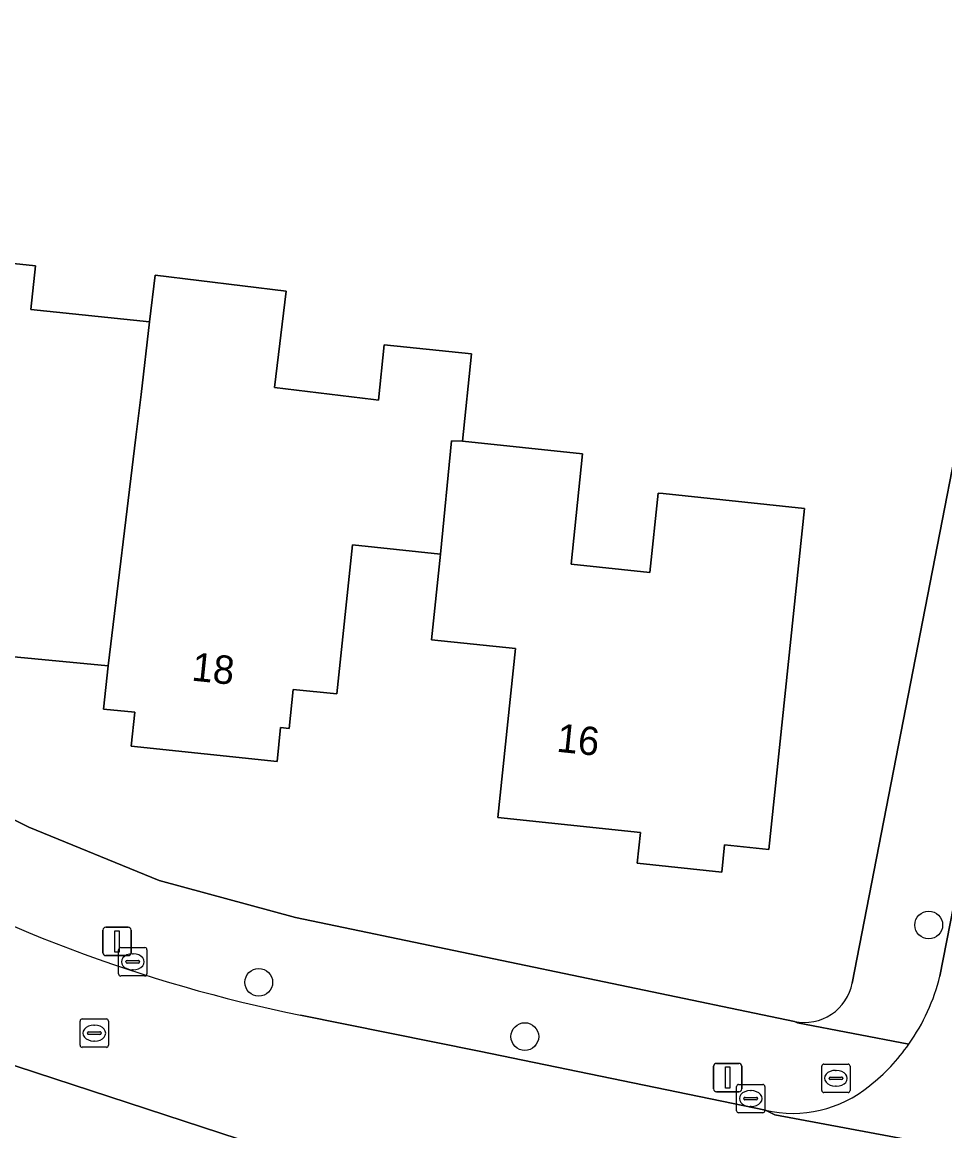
# Model space of a CAD drawing. Extents: x 162396 to 163643, y 386452 to 387406.
# Drawn here: x 162942.76 to 162975.29, y 386904.9 to 386943.96 of the extents above; entities that cross this region are included whole.
import ezdxf

# ---------------------------------------------------------------- set-up
doc = ezdxf.new("R2010")
doc.units = 0
for name, color, linetype in [('IMGEO_Boom', 7, 'Continuous'), ('IMGEO_Brandkraan', 7, 'Continuous'), ('IMGEO_Erf', 7, 'Continuous'), ('IMGEO_Kolk', 7, 'Continuous'), ('IMGEO_Lichtmast', 7, 'Continuous'), ('IMGEO_Pand', 7, 'Continuous'), ('IMGEO_Pand_nummerreeks', 7, 'Continuous'), ('IMGEO_Rijbaan_lokaal_open', 7, 'Continuous'), ('IMGEO_Rioolput', 7, 'Continuous'), ('IMGEO_Voetpad_open', 7, 'Continuous')]:
    doc.layers.add(name, color=color, linetype=linetype)

msp = doc.modelspace()

# ---------------------------------------------------------------- linework, layer by layer
at = {"layer": 'IMGEO_Boom'}
for centre in [(162974.721, 386912.151), (162951.105, 386910.133), (162960.482, 386908.221)]:
    msp.add_circle(centre, 0.489, dxfattribs=at)
at = {"layer": 'IMGEO_Brandkraan'}
for p, q in [((162970.948, 386906.324), (162970.948, 386907.176)), ((162971.023, 386907.25), (162971.875, 386907.25)), ((162971.436, 386907.03), (162971.461, 386907.03)), ((162971.949, 386907.176), (162971.949, 386906.324)), ((162971.207, 386906.744), (162971.207, 386906.756)), ((162971.645, 386906.707), (162971.247, 386906.707)), ((162971.25, 386906.793), (162971.648, 386906.793)), ((162971.691, 386906.756), (162971.691, 386906.744)), ((162971.875, 386906.25), (162971.023, 386906.25)), ((162971.459, 386906.47), (162971.434, 386906.47))]:
    msp.add_line(p, q, dxfattribs=at)
for points in [[(162970.948, 386906.324), (162970.948, 386907.176)], [(162971.023, 386907.25), (162971.875, 386907.25)], [(162971.949, 386907.176), (162971.949, 386906.324)], [(162971.875, 386906.25), (162971.023, 386906.25)]]:
    msp.add_lwpolyline(points, dxfattribs=at)
for centre, radius, start, end in [((162971.025, 386907.174), 0.0765, 91.552, 178.448), ((162971.025, 386907.174), 0.0765, 91.552, 178.448), ((162971.873, 386907.174), 0.0765, 1.552, 88.448), ((162971.873, 386907.174), 0.0765, 1.552, 88.448), ((162971.247, 386906.753), 0.0403, 85.8775, 175.7526), ((162971.244, 386906.743), 0.0366, 178.938, 274.7102), ((162971.648, 386906.75), 0.043, 264.8664, 352.4533), ((162971.652, 386906.755), 0.0386, 1.7309, 96.639), ((162971.025, 386906.326), 0.0765, 181.552, 268.448), ((162971.025, 386906.326), 0.0765, 181.552, 268.448), ((162971.873, 386906.326), 0.0765, 271.552, 358.448), ((162971.873, 386906.326), 0.0765, 271.552, 358.448)]:
    msp.add_arc(centre, radius, start, end, dxfattribs=at)
for centre, major_axis, ratio, start_param, end_param in [((162971.435, 386906.75), (-0.387, 0.002), 0.722429, 4.712389, 7.853982), ((162971.46, 386906.75), (-0.39, 0.002), 0.717154, 1.570796, 4.712389)]:
    msp.add_ellipse(centre, major_axis=major_axis, ratio=ratio, start_param=start_param, end_param=end_param, dxfattribs=at)
at = {"layer": 'IMGEO_Erf'}
for points in [[(162972.023, 386910.108), (162989.528, 387000)], [(162938.889, 386935.832), (162943.233, 386935.379), (162943.073, 386933.841), (162947.256, 386933.404), (162947.456, 386935.045), (162952.066, 386934.484), (162951.653, 386931.092), (162955.145, 386930.667), (162955.326, 386930.645), (162955.529, 386932.589), (162958.603, 386932.269), (162958.283, 386929.195), (162962.519, 386928.753), (162962.113, 386924.861), (162964.894, 386924.571), (162965.185, 386927.367), (162965.363, 386927.348), (162970.336, 386926.83), (162969.083, 386914.816), (162967.524, 386914.979), (162967.423, 386914.016), (162964.444, 386914.327), (162964.558, 386915.416), (162959.532, 386915.94), (162960.153, 386921.893), (162957.193, 386922.202), (162957.508, 386925.217), (162954.404, 386925.541), (162953.856, 386920.291), (162952.313, 386920.452), (162952.17, 386919.077), (162951.872, 386919.108), (162951.748, 386917.916), (162946.608, 386918.451), (162946.732, 386919.644), (162945.637, 386919.758), (162945.795, 386921.277), (162937.784, 386922.045)], [(162905.757, 386934.385), (162943, 386915.598), (162947.592, 386913.72), (162952.4, 386912.414), (162969.989, 386908.754)]]:
    msp.add_lwpolyline(points, dxfattribs=at)
msp.add_arc((162970.34, 386910.431), 1.714, 258.1769, 349.1251, dxfattribs=at)
at = {"layer": 'IMGEO_Kolk'}
for p, q in [((162946.238, 386911.355), (162947.09, 386911.355)), ((162946.163, 386910.429), (162946.163, 386911.281)), ((162946.651, 386911.135), (162946.676, 386911.135)), ((162947.164, 386911.281), (162947.164, 386910.429)), ((162946.422, 386910.849), (162946.422, 386910.861)), ((162946.86, 386910.812), (162946.462, 386910.812)), ((162946.465, 386910.898), (162946.863, 386910.898)), ((162946.674, 386910.575), (162946.649, 386910.575)), ((162946.906, 386910.861), (162946.906, 386910.849)), ((162947.09, 386910.355), (162946.238, 386910.355)), ((162967.944, 386905.61), (162967.944, 386906.462)), ((162968.019, 386906.536), (162968.871, 386906.536)), ((162968.432, 386906.316), (162968.457, 386906.316)), ((162968.945, 386906.462), (162968.945, 386905.61)), ((162968.203, 386906.03), (162968.203, 386906.042)), ((162968.641, 386905.993), (162968.243, 386905.993)), ((162968.246, 386906.079), (162968.644, 386906.079)), ((162968.687, 386906.042), (162968.687, 386906.03)), ((162968.871, 386905.536), (162968.019, 386905.536)), ((162968.455, 386905.756), (162968.43, 386905.756))]:
    msp.add_line(p, q, dxfattribs=at)
for points in [[(162946.238, 386911.355), (162947.09, 386911.355)], [(162946.163, 386910.429), (162946.163, 386911.281)], [(162947.164, 386911.281), (162947.164, 386910.429)], [(162947.09, 386910.355), (162946.238, 386910.355)], [(162967.944, 386905.61), (162967.944, 386906.462)], [(162968.019, 386906.536), (162968.871, 386906.536)], [(162968.945, 386906.462), (162968.945, 386905.61)], [(162968.871, 386905.536), (162968.019, 386905.536)]]:
    msp.add_lwpolyline(points, dxfattribs=at)
for centre, radius, start, end in [((162946.24, 386911.279), 0.0765, 91.552, 178.448), ((162946.24, 386911.279), 0.0765, 91.552, 178.448), ((162947.088, 386911.279), 0.0765, 1.552, 88.448), ((162947.088, 386911.279), 0.0765, 1.552, 88.448), ((162946.462, 386910.858), 0.0403, 85.8775, 175.7526), ((162946.459, 386910.848), 0.0366, 178.938, 274.7102), ((162946.863, 386910.855), 0.043, 264.8664, 352.4533), ((162946.867, 386910.86), 0.0386, 1.7309, 96.639), ((162946.24, 386910.431), 0.0765, 181.552, 268.448), ((162946.24, 386910.431), 0.0765, 181.552, 268.448), ((162947.088, 386910.431), 0.0765, 271.552, 358.448), ((162947.088, 386910.431), 0.0765, 271.552, 358.448), ((162968.021, 386906.46), 0.0765, 91.552, 178.448), ((162968.021, 386906.46), 0.0765, 91.552, 178.448), ((162968.869, 386906.46), 0.0765, 1.552, 88.448), ((162968.869, 386906.46), 0.0765, 1.552, 88.448), ((162968.243, 386906.039), 0.0403, 85.8775, 175.7526), ((162968.24, 386906.029), 0.0366, 178.938, 274.7102), ((162968.644, 386906.036), 0.043, 264.8664, 352.4533), ((162968.648, 386906.041), 0.0386, 1.7309, 96.639), ((162968.021, 386905.612), 0.0765, 181.552, 268.448), ((162968.021, 386905.612), 0.0765, 181.552, 268.448), ((162968.869, 386905.612), 0.0765, 271.552, 358.448), ((162968.869, 386905.612), 0.0765, 271.552, 358.448)]:
    msp.add_arc(centre, radius, start, end, dxfattribs=at)
for centre, major_axis, ratio, start_param, end_param in [((162946.65, 386910.855), (-0.387, 0.002), 0.722429, 4.712389, 7.853982), ((162946.675, 386910.855), (-0.39, 0.002), 0.717154, 1.570796, 4.712389), ((162968.431, 386906.036), (-0.387, 0.002), 0.722429, 4.712389, 7.853982), ((162968.456, 386906.036), (-0.39, 0.002), 0.717154, 1.570796, 4.712389)]:
    msp.add_ellipse(centre, major_axis=major_axis, ratio=ratio, start_param=start_param, end_param=end_param, dxfattribs=at)
at = {"layer": 'IMGEO_Lichtmast'}
for p, q in [((162945.611, 386911.172), (162945.611, 386911.972)), ((162945.611, 386911.972), (162945.611, 386911.172)), ((162945.711, 386912.072), (162946.501, 386912.072)), ((162946.501, 386912.072), (162945.711, 386912.072)), ((162946.601, 386911.972), (162946.601, 386911.172)), ((162946.601, 386911.172), (162946.601, 386911.972)), ((162946.501, 386911.072), (162945.711, 386911.072)), ((162945.711, 386911.072), (162946.501, 386911.072)), ((162967.138, 386906.376), (162967.138, 386907.176)), ((162967.138, 386907.176), (162967.138, 386906.376)), ((162967.238, 386907.276), (162968.028, 386907.276)), ((162968.028, 386907.276), (162967.238, 386907.276)), ((162968.128, 386907.176), (162968.128, 386906.376)), ((162968.128, 386906.376), (162968.128, 386907.176)), ((162968.028, 386906.276), (162967.238, 386906.276)), ((162967.238, 386906.276), (162968.028, 386906.276))]:
    msp.add_line(p, q, dxfattribs=at)
for points in [[(162946.031, 386911.947), (162946.181, 386911.947), (162946.181, 386911.197), (162946.031, 386911.197), (162946.031, 386911.947)], [(162967.558, 386907.151), (162967.708, 386907.151), (162967.708, 386906.401), (162967.558, 386906.401), (162967.558, 386907.151)]]:
    msp.add_lwpolyline(points, dxfattribs=at)
for centre, start, end in [((162945.711, 386911.972), 90, 180), ((162945.711, 386911.972), 90, 180), ((162946.501, 386911.972), 0, 90), ((162946.501, 386911.972), 360, 90), ((162945.711, 386911.172), 180, 270), ((162945.711, 386911.172), 180, 270), ((162946.501, 386911.172), 270, 0), ((162946.501, 386911.172), 270, 0), ((162967.238, 386907.176), 90, 180), ((162967.238, 386907.176), 90, 180), ((162968.028, 386907.176), 0, 90), ((162968.028, 386907.176), 360, 90), ((162967.238, 386906.376), 180, 270), ((162967.238, 386906.376), 180, 270), ((162968.028, 386906.376), 270, 0), ((162968.028, 386906.376), 270, 0)]:
    msp.add_arc(centre, 0.1, start, end, dxfattribs=at)
at = {"layer": 'IMGEO_Pand'}
for points in [[(162947.256, 386933.404), (162943.073, 386933.841), (162943.233, 386935.379), (162938.889, 386935.832), (162938.919, 386936.121), (162935.975, 386936.428), (162935.219, 386929.208), (162938.496, 386928.866), (162937.914, 386923.288), (162937.784, 386922.045), (162945.795, 386921.277), (162946.776, 386929.332), (162946.954, 386930.845)], [(162954.404, 386925.541), (162957.508, 386925.217), (162957.898, 386929.209), (162958.283, 386929.195), (162958.603, 386932.269), (162955.529, 386932.589), (162955.326, 386930.645), (162955.145, 386930.667), (162951.653, 386931.092), (162952.066, 386934.484), (162947.456, 386935.045), (162947.256, 386933.404), (162946.954, 386930.845), (162946.776, 386929.332), (162945.795, 386921.277), (162945.637, 386919.758), (162946.732, 386919.644), (162946.608, 386918.451), (162951.748, 386917.916), (162951.872, 386919.108), (162952.17, 386919.077), (162952.313, 386920.452), (162953.856, 386920.291)], [(162957.898, 386929.209), (162957.508, 386925.217), (162957.193, 386922.202), (162960.153, 386921.893), (162959.532, 386915.94), (162964.558, 386915.416), (162964.444, 386914.327), (162967.423, 386914.016), (162967.524, 386914.979), (162969.083, 386914.816), (162970.336, 386926.83), (162965.363, 386927.348), (162965.185, 386927.367), (162964.894, 386924.571), (162962.113, 386924.861), (162962.519, 386928.753), (162958.283, 386929.195)]]:
    msp.add_lwpolyline(points, close=True, dxfattribs=at)
at = {"layer": 'IMGEO_Rijbaan_lokaal_open'}
for points in [[(162993.351, 387003.708), (162992.593, 387000), (162990.936, 386991.471), (162990.218, 386987.772), (162987.431, 386973.419), (162985.908, 386965.577), (162983.057, 386950.899), (162982.357, 386947.293), (162975.116, 386910.354)], [(162901.826, 386926.95), (162904.027, 386925.887), (162937.007, 386909.322), (162938.667, 386908.445), (162951.708, 386904.178), (162954.151, 386903.61), (163000, 386894.601), (163000.585, 386894.482)], [(163015.114, 386895.272), (163013.969, 386895.696), (163009.769, 386897.129), (163003.361, 386898.96), (163000, 386899.64), (162985.263, 386902.621), (162985.093, 386902.521), (162969.299, 386905.46), (162968.963, 386905.626), (162958.875, 386907.712), (162952.574, 386908.978)], [(162951.708, 386904.178), (162938.667, 386908.445)], [(162968.963, 386905.626), (162969.299, 386905.46), (162985.093, 386902.521), (162985.263, 386902.621)]]:
    msp.add_lwpolyline(points, dxfattribs=at)
for centre, radius, start, end in [((162962.901, 386960.241), 52.293, 240.0812, 258.6099), ((162968.219, 386912.053), 7.103, 324.7686, 346.1636), ((162968.216, 386912.041), 7.099, 308.466, 324.8575), ((162969.93, 386909.768), 4.253, 256.8567, 309.438)]:
    msp.add_arc(centre, radius, start, end, dxfattribs=at)
at = {"layer": 'IMGEO_Rioolput'}
for p, q in [((162944.806, 386907.916), (162944.806, 386908.768)), ((162944.881, 386908.842), (162945.733, 386908.842)), ((162945.294, 386908.622), (162945.319, 386908.622)), ((162945.807, 386908.768), (162945.807, 386907.916)), ((162945.065, 386908.336), (162945.065, 386908.348)), ((162945.503, 386908.299), (162945.105, 386908.299)), ((162945.108, 386908.385), (162945.506, 386908.385)), ((162945.549, 386908.348), (162945.549, 386908.336)), ((162945.733, 386907.842), (162944.881, 386907.842)), ((162945.317, 386908.062), (162945.292, 386908.062))]:
    msp.add_line(p, q, dxfattribs=at)
for points in [[(162944.806, 386907.916), (162944.806, 386908.768)], [(162944.881, 386908.842), (162945.733, 386908.842)], [(162945.807, 386908.768), (162945.807, 386907.916)], [(162945.733, 386907.842), (162944.881, 386907.842)]]:
    msp.add_lwpolyline(points, dxfattribs=at)
for centre, radius, start, end in [((162944.883, 386908.766), 0.0765, 91.552, 178.448), ((162944.883, 386908.766), 0.0765, 91.552, 178.448), ((162945.731, 386908.766), 0.0765, 1.552, 88.448), ((162945.731, 386908.766), 0.0765, 1.552, 88.448), ((162945.105, 386908.345), 0.0403, 85.8775, 175.7526), ((162945.102, 386908.335), 0.0366, 178.938, 274.7102), ((162945.506, 386908.342), 0.043, 264.8664, 352.4533), ((162945.51, 386908.347), 0.0386, 1.7309, 96.639), ((162944.883, 386907.918), 0.0765, 181.552, 268.448), ((162944.883, 386907.918), 0.0765, 181.552, 268.448), ((162945.731, 386907.918), 0.0765, 271.552, 358.448), ((162945.731, 386907.918), 0.0765, 271.552, 358.448)]:
    msp.add_arc(centre, radius, start, end, dxfattribs=at)
for centre, major_axis, ratio, start_param, end_param in [((162945.293, 386908.342), (-0.387, 0.002), 0.722429, 4.712389, 7.853982), ((162945.318, 386908.342), (-0.39, 0.002), 0.717154, 1.570796, 4.712389)]:
    msp.add_ellipse(centre, major_axis=major_axis, ratio=ratio, start_param=start_param, end_param=end_param, dxfattribs=at)
at = {"layer": 'IMGEO_Voetpad_open'}
for points in [[(162990.536, 387005.429), (162989.528, 387000), (162972.023, 386910.108)], [(162975.116, 386910.354), (162982.357, 386947.293)], [(162952.4, 386912.414), (162947.592, 386913.72), (162943, 386915.598), (162905.757, 386934.385)], [(162974.021, 386907.955), (162970.096, 386908.707), (162969.989, 386908.754), (162952.4, 386912.414)], [(162952.574, 386908.978), (162958.875, 386907.712), (162968.963, 386905.626)], [(162969.989, 386908.754), (162970.096, 386908.707), (162974.021, 386907.955)]]:
    msp.add_lwpolyline(points, dxfattribs=at)
for centre, radius, start, end in [((162962.901, 386960.241), 52.293, 240.0812, 258.6099), ((162968.219, 386912.053), 7.103, 324.7686, 346.1636), ((162970.34, 386910.431), 1.714, 258.1769, 349.1251), ((162968.216, 386912.041), 7.099, 308.466, 324.8575), ((162969.93, 386909.768), 4.253, 256.8567, 309.438)]:
    msp.add_arc(centre, radius, start, end, dxfattribs=at)

# ---------------------------------------------------------------- texts
at = {"layer": 'IMGEO_Pand_nummerreeks'}
for s, rotation, p in [('18', 354.0584, (162948.71, 386920.766)), ('16', 354.048, (162961.575, 386918.26))]:
    msp.add_text(s, height=1, rotation=rotation, dxfattribs=at).set_placement(p)

doc.saveas('drawing.dxf')
